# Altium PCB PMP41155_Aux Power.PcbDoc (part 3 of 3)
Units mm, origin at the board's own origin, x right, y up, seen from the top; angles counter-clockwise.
Board outline 40.5 x 70.5 mm, 6 copper layers (Top Layer, Signal Layer 1, Signal Layer 2, Signal Layer 3, Signal Layer 4, Bottom Layer), stack 1.573 mm thick; 130 components, 63 nets, 392 pads, 295 vias.
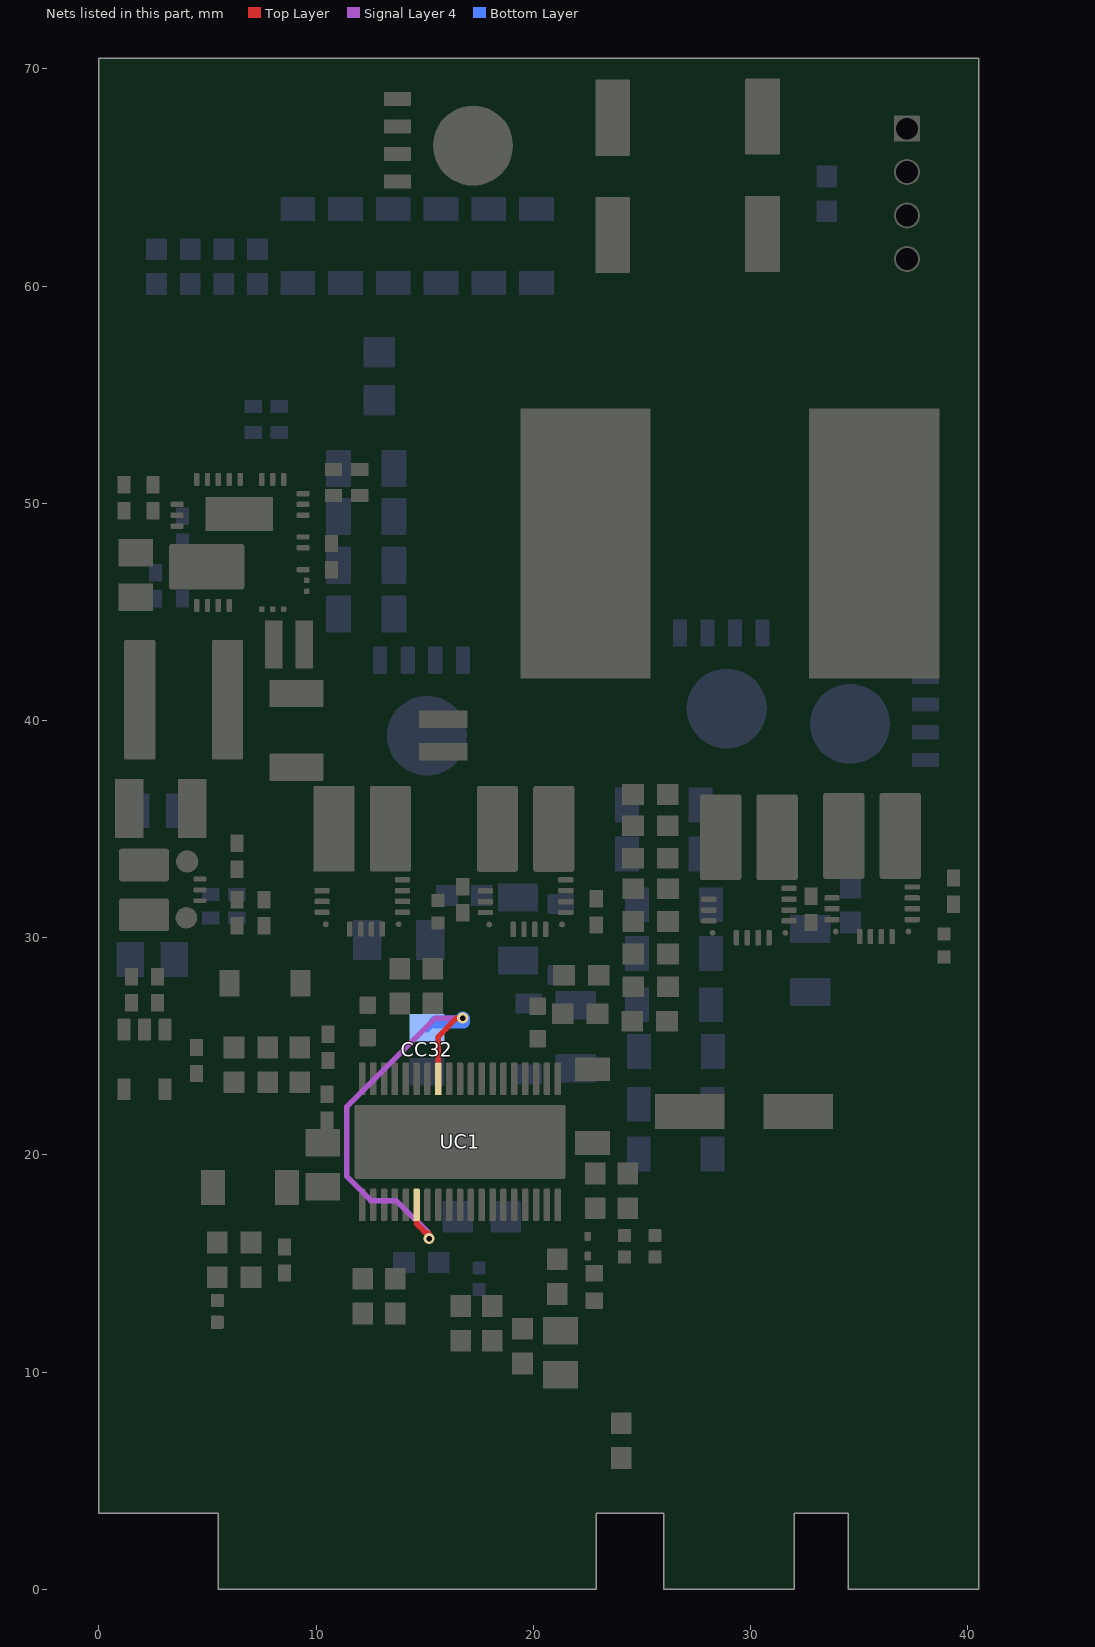
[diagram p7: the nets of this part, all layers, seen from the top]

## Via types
v1: diameter 0.508, hole 0.254, Top Layer to Bottom Layer, 138 vias
v2: diameter 0.5, hole 0.2, Top Layer to Bottom Layer, tented both sides, 64 vias
v3: diameter 0.5, hole 0.2, Top Layer to Bottom Layer, 48 vias
v4: diameter 0.6, hole 0.3, Top Layer to Bottom Layer, 29 vias
v5: diameter 1.27, hole 0.711, Top Layer to Bottom Layer, 8 vias
v6: diameter 0.5, hole 0.3, Top Layer to Bottom Layer, 7 vias
v7: diameter 0.508, hole 0.254, Top Layer to Bottom Layer, tented both sides, 1 vias

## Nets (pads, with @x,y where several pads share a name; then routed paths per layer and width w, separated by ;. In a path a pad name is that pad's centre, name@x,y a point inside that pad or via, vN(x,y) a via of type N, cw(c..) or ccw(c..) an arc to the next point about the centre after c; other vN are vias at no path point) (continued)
VCC_DISCH: CC32.1 UC1.6 UC1.31 | length 22.1
  Top Layer w0.254: UC1.6@14.625,17.7 14.625,16.827 14.632,16.827 14.959,16.5 14.959,16.491 15.048,16.402 v1@15.184,16.402 ; UC1.31@15.625,23.5 15.625,25.453 16.471,26.3 v1(16.75,26.3)
  Signal Layer 4 w0.254: v1@15.184,16.402 13.686,17.9 12.525,17.9 11.4,19.025 11.4,22.215 15.485,26.3 v1(16.75,26.3)
  Bottom Layer w0.254: CC32.1@15.1,25.766 CC32.1@15.48,26.146
  Bottom Layer w0.6: CC32.1@15.499,26.128 16.778,26.128 16.778,26.272 v1(16.75,26.3)
  other v1: 15.2,16.15
pads on no net: QC1.1 QC1.5 QC1.9 QC1.10 QC1.11 QC1.12 QC1.13 QC1.15 QC2.1 QC2.5 QC2.9 QC2.10 QC2.11 QC2.12 QC2.13 QC2.15 QC3.1 QC3.5 QC3.9 QC3.10 QC3.11 QC3.12 QC3.13 QC3.15 QC4.1 QC4.5 QC4.9 QC4.10 QC4.11 QC4.12 QC4.13 QC4.15 U1.7 U1.8 U1.10 U2.4 U3.2 U3.5 UC1.2 UC1.5 UC1.8 UC1.9 UC1.21 UC1.24 UC1.28 UC1.33
copper on no net:
  other v3: 1.585,32.85 2.085,32.85 2.585,32.85 1.585,33.85 2.085,33.85 2.585,33.85

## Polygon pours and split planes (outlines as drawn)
NetC3_1 on Top Layer "TOP_LAYER_NETC3_1_P262" (solid, pour order 262): 6.65,46 6.75,46.1 6.75,48.1 6.55,48.3 3.2,48.3 2.85,47.95 2.85,44.25 2.55,43.95 0.8,43.95 0.5,43.65 0.5,38.6 1.05,38.05 2.75,38.05 3.8,39.1 3.8,46
12V on Top Layer "TOP_LAYER_12V_P261" (solid, pour order 261): 11.95,69 12.45,69.5 14,69.5 14.35,69.15 14.35,64.35 14,64 12.3,64 11.95,64.35
SGND on Top Layer "TOP_LAYER_SGND_P258" (solid, pour order 258): 0.75,37.35 2.5,37.35 2.65,37.2 2.65,34.7 2.55,34.6 0.75,34.6
SGND on Top Layer "TOP_LAYER_SGND_P257" (solid, pour order 257): 10.15,38.55 11,39.4 11.7,39.4 12.05,39.05 12.05,37.4 11.85,37.2 7.85,37.2 7.85,38.55
12V on Top Layer "TOP_LAYER_12V_P256" (solid, pour order 256): 7.9,41.85 7.95,41.9 8.85,41.9 9.05,42.1 9.05,44.6 9.8,44.6 11.95,42.45 11.95,40.8 11.75,40.6 7.9,40.6 7.9,41.9
12V on Top Layer "TOP_LAYER_12V_P255" (solid, pour order 255): 4.65,33.1 4.65,34.3 5.65,35.3 5.65,37.3 3.65,37.3 3.5,37.15 3.5,32.5 3.95,32.5 3.95,33.1
5V on Top Layer "TOP_LAYER_5V_P252" (solid, pour order 252): 0.95,31.8 3.2,31.8 3.2,27.7 0.95,27.7
SGND on Top Layer "TOP_LAYER_SGND_P251" (solid, pour order 251): 4.25,45.6 4.45,45.8 6.5,45.8 6.8,45.5 6.8,44.5 6.55,44.25 4.4,44.25 4.25,44.4
NetL1_2 on Top Layer "TOP_LAYER_NETL1_2_P250" (solid, pour order 250): 8.45,44.6 7.4,44.6 6.8,44 5.55,44 5.5,43.95 5.5,38.35 6.95,38.35 7.1,38.5 7.1,41.95 7.55,42.4 8.45,42.4
12VFAN on Top Layer "TOP_LAYER_12VFAN_P249" (solid, pour order 249): 39.25,64.2 39.6,63.85 39.6,62.7 39.25,62.35 34.85,62.35 32.85,64.35 15.35,64.35 14.65,65.05 14.65,69.4 14.7,69.4 14.85,69.55 31.45,69.55 36.8,64.2
SGND on Top Layer "TOP_LAYER_SGND_P248" (solid, pour order 248): 34.6,62.15 39.1,62.15 39.55,61.7 39.55,59.75 39.25,59.45 22.8,59.45 22.4,59.85 22.4,63.7 22.8,64.1 32.65,64.1
VBATAUX on Top Layer "TOP_LAYER_VBATAUX_P246" (solid, pour order 246): 7.245,54.108 10.708,54.108 11.5,54.9 11.5,59.4 11.3,59.6 7.45,59.6 7.245,59.395
SGND on Top Layer "TOP_LAYER_SGND_P245" (solid, pour order 245): 1.2,69.15 6.35,69.15 8.997,69.15 9.8,68.347 9.8,64.25 9.05,63.5 6.74,63.5 6.45,63.138 6.45,52.55 1.8,52.55 1,53.35 1,68.95 1.1,69.05
CSB_DISCH on Top Layer "TOP_LAYER_CSB_DISCH_P239" (solid, pour order 239): 14.75,39.65 26.65,39.65 28,41 28,57 27.45,57.55 19.35,57.55 14.7,52.9 14.7,39.75
VAUX on Top Layer "TOP_LAYER_VAUX_P238" (solid, pour order 238): 29.6,32.5 29.6,36.45 28.35,37.7 28.35,38.7 27.9,39.15 25.65,39.15 25.25,38.75 25.25,24.3 30.1,24.3 30.1,25.95 27.5,28.55 27.5,31.65 28.75,31.65
SGND on Top Layer "TOP_LAYER_SGND_P230" (solid, pour order 230): 30.55,26.1 31.85,27.4 39.6,27.4 39.6,1.5 39.55,1.45 39.4,1.6 35.1,1.6 35.1,4.05 30.55,8.6
VAUX on Top Layer "TOP_LAYER_VAUX_P228" (solid, pour order 228): 27.05,4.5 27.05,20.95 27,20.95 26.75,21.2 24.9,21.2 22.7,23.4 21.95,23.4 21.95,24.5 30.1,24.5 30.1,5.15 29.45,4.5
SGND on Top Layer "TOP_LAYER_SGND_P227" (solid, pour order 227): 6.4,69 6.4,67.8 3.4,67.8 3.4,69
VBATAUX on Top Layer "TOP_LAYER_VBATAUX_P225" (solid, pour order 225): 9.099,55.602 9.099,54.902 7.299,54.902 7.299,55.602
SGND on Top Layer "TOP_LAYER_SGND_P226" (solid, pour order 226): 6.4,53.95 6.4,52.75 3.4,52.75 3.4,53.95
VBATAUX on Top Layer "TOP_LAYER_VBATAUX_P224" (solid, pour order 224): 9.1,56.85 9.1,56.15 7.3,56.15 7.3,56.85
VBATAUX on Top Layer "TOP_LAYER_VBATAUX_P223" (solid, pour order 223): 9.099,58.102 9.099,57.402 7.299,57.402 7.299,58.102
VBATAUX on Top Layer "TOP_LAYER_VBATAUX_P222" (solid, pour order 222): 9.1,59.35 9.1,58.65 7.3,58.65 7.3,59.35
no net on Top Layer "TOP_LAYER_NONET_P221" (solid, pour order 221): 9.099,60.602 9.099,59.902 7.299,59.902 7.299,60.602
no net on Top Layer "TOP_LAYER_NONET_P220" (solid, pour order 220): 9.1,61.85 9.1,61.15 7.3,61.15 7.3,61.85
no net on Top Layer "TOP_LAYER_NONET_P219" (solid, pour order 219): 9.099,63.102 9.099,62.402 7.299,62.402 7.299,63.102
SGND on Top Layer "TOP_LAYER_SGND_P218" (solid, pour order 218): 9.1,64.35 9.1,63.65 7.3,63.65 7.3,64.35
SGND on Top Layer "TOP_LAYER_SGND_P217" (solid, pour order 217): 9.099,65.602 9.099,64.902 7.299,64.902 7.299,65.602
SGND on Top Layer "TOP_LAYER_SGND_P216" (solid, pour order 216): 9.1,66.85 9.1,66.15 7.3,66.15 7.3,66.85
CSA_DISCH on Top Layer "TOP_LAYER_CSA_DISCH_P148" (solid, remove dead copper, pour order 148): 12.45,33.079 19.6,33.079 19.6,36.95 20.35,37.7 20.35,39.35 14.543,39.35 12.45,37.257
SGND on Top Layer "TOP_LAYER_SGND_P211" (solid, remove dead copper, pour order 211): 0.5,3.5 20.2,3.5 25.4,8.7 25.4,20.25 23.336,22.314 0.5,22.314
SGND on Top Layer "TOP_LAYER_SGND_P176" (solid, pour order 176): 35.7,36.647 37.693,36.647 39.023,37.977 39.532,37.977 39.532,34.074 38.962,33.503 38.282,33.503 37.532,32.753 35.7,32.753
SW2 on Top Layer "TOP_LAYER_SW2_P190" (solid, pour order 190): 39.2,54.5 40.048,53.652 40.052,39.502 37.702,37.152 37.093,37.152 37.093,37.043 36.8,36.75 36.8,32.75 30.15,32.75 30.15,36.35 28.85,37.65 28.85,52.65 30.7,54.5
SW2 on Top Layer "TOP_LAYER_SW2_P164" (solid, pour order 164): 29.59,36.662 36.454,36.662 36.454,32.626 33.655,32.626 33.319,32.962 32.464,32.962 32.06,32.558 29.769,32.558 29.55,32.777 29.55,36.622
SGND on Top Layer "TOP_LAYER_SGND_P177" (solid, pour order 177): 23.45,33.068 23.65,32.868 23.65,24.05 25.05,24.05 25.05,30.25 25.05,38.85 24.76,39.14 22.09,39.14 19.8,36.85 19.8,33.068
5V on Top Layer "5V" (solid, remove dead copper, pour order 42): 6,11.05 6,9.85 6.2,9.65 11.184,9.65 11.217,9.683 11.217,10.964 10.981,11.2 6.15,11.2
SGND on Bottom Layer "BOTTOM_LAYER_SGND_P264" (solid, pour order 264): 4.85,50.4 7.95,50.4 8.25,50.1 8.25,48.4 7.9,48.05 6.8,48.05 6.45,47.7 6.45,45.25 4.7,45.25 4.45,45.5 4.45,50.05 4.85,50.45
SGND on Bottom Layer "BOTTOM_LAYER_SGND_P263" (solid, pour order 263): 5.8,46 6.9,44.9 6.9,43.25 6.4,42.75 0.7,42.75 0.5,42.95 0.5,45.75 0.75,46
12V on Bottom Layer "BOTTOM_LAYER_12V_P260" (solid, pour order 260): 4.65,33.1 4.65,34.3 5.65,35.3 5.65,37.3 3.65,37.3 3.05,36.7 3.05,32.5 3.95,32.5 3.95,33.1
VBATAUX on Bottom Layer "BOTTOM_LAYER_VBATAUX_P259" (solid, pour order 259): 1,60.2 1.5,60.7 20.85,60.7 21.9,59.65 21.9,57.4 14.6,57.4 13.35,56.15 11.55,56.15 11.1,55.7 11.1,54.4 10.75,54.05 10.7,54.1 9.55,54.1 9.55,54.15 9.15,54.55 9.15,56.3 6.35,59.1 1.4,59.1 1,59.5
5V on Bottom Layer "BOTTOM_LAYER_5V_P254" (solid, pour order 254): 2.75,31.8 2.85,31.7 2.85,30.2 2.55,29.9 2.55,28.65 2.1,28.2 0.8,28.2 0.8,31.7 0.9,31.8
SGND on Bottom Layer "BOTTOM_LAYER_SGND_P253" (solid, pour order 253): 2.85,29.8 4.1,29.8 4.25,29.65 4.25,26.85 4,26.6 2.95,26.6 2.85,26.7
SGND on Bottom Layer "BOTTOM_LAYER_SGND_P247" (solid, pour order 247): 1,68.95 1.55,69.5 39.05,69.5 39.5,69.05 39.5,64.7 36.05,61.25 1.55,61.25 1,61.8
VAUX on Bottom Layer "BOTTOM_LAYER_VAUX_P243" (solid, pour order 243): 7.1,45.35 9.25,45.35 9.85,44.75 9.85,44.25 10,44.1 11.6,44.1 12.2,44.7 12.2,52 11.8,52.4 10,52.4 8.5,50.9 8.5,48.25 8.15,47.9 7.05,47.9 6.95,47.8 6.95,45.5
SGND on Bottom Layer "BOTTOM_LAYER_SGND_P241" (solid, pour order 241): 18.35,32.5 18.35,31.2 20.25,31.2 20.25,32.2 20.55,32.5 25.6,32.5 25.6,41.45 14.4,52.65 12.6,52.65 12.6,44.7 12.6,42.15 13.15,41.6 18.35,41.6 19.95,40 19.95,32.8 19.65,32.5
SGND on Bottom Layer "BOTTOM_LAYER_SGND_P046" (solid, pour order 46): 37.304,42.545 37.309,42.55 39.65,42.55 39.95,42.25 39.95,30.45 39.45,29.95 36.15,29.95 35.85,30.25 35.85,36.7 36.4,37.25 37.15,37.25 37.3,37.4 37.3,42.55
SGND on Bottom Layer "BOTTOM_LAYER_SGND_P054" (solid, pour order 54): 25.6,19.2 25.6,37.3 25.3,37.6 23.75,37.6 23.45,37.3 23.45,19.8 24.05,19.2
SGND on Bottom Layer "BOTTOM_LAYER_SGND_P237" (solid, pour order 237): 30.55,26.85 31.85,28.15 39.6,28.15 39.6,1.5 39.55,1.45 39.4,1.6 35.1,1.6 35.1,4.05 30.55,8.6
SGND on Bottom Layer "BOTTOM_LAYER_SGND_P236" (solid, remove dead copper, pour order 236): 0.45,4.25 1.2,3.5 22.2,3.5 23.027,4.327 23.027,22.123 22.836,22.314 2.193,22.314 0.45,20.404
VAUX on Bottom Layer "Bottom Layer-48V_DISCH_OUT" (solid, remove dead copper, pour order 180): 26.189,42.734 25.78,42.325 25.78,32.35 26.565,31.797 26.565,24.513 23.9,21.849 23.9,9.336 23.9,4.082 24.109,3.873 25.259,3.873 29.345,3.873 29.65,4.177 29.65,32.871 29.95,33.158 29.95,35.998 31.544,37.592 31.544,42.262 31.071,42.735 26.215,42.735
NetC2_2 on Bottom Layer "BOTTOM_LAYER_NETC2_2_P234" (solid, remove dead copper, pour order 234): 17.157,32.42 17.157,29.505 18.362,28.3 20.212,28.3 20.212,29.6 18.912,29.6 18.112,30.4 18.123,30.411 18.123,32.42
SW2 on Bottom Layer "Bottom Layer-SW2" (solid, pour order 215): 28.535,32.955 29.872,31.619 34.776,31.619 35.645,32.488 35.645,36.654 36.348,37.356 39.75,37.356 39.75,56.05 38.3,57.5 27.5,57.5 26.495,56.495 26.495,43.35 31.995,43.35 31.995,36.431 29.01,36.431 28.535,35.956
CSA_DISCH on Bottom Layer "BOTTOM_LAYER_CSA_DISCH_P144" (solid, pour order 144): 12.328,41.078 12.6,41.35 17.7,41.35 19.44,39.61 19.44,32.744 12.328,32.744
5V on Bottom Layer "5V" (solid, remove dead copper, pour order 194): 6.15,11.2 5.95,11 5.95,9.7 6.15,9.5 11.354,9.5 11.55,9.696 11.55,11.967 11.217,12.3 10.406,12.3 10.191,12.085 10.191,11.691 9.7,11.2
NetC1_2 on Bottom Layer "BOTTOM_LAYER_NETC1_2_P195" (solid, pour order 195): 35.325,31.2 35.325,30.225 34.905,29.805 31.79,29.805 31.79,31.2
VBATAUX on Signal Layer 3 "SIGNAL_LAYER_3_VBATAUX_P244" (solid, pour order 244): 11.9,33.4 11.9,44.7 20,52.8 20,62.65 15.6,67.05 8.15,67.05 5.5,64.4 5.5,37.5 9.6,33.4
SGND on Signal Layer 3 "SIGNAL_LAYER_3_SGND_P232" (solid, pour order 232): 26,24.65 28.75,27.4 39.6,27.4 39.6,1.5 39.55,1.45 39.4,1.6 35.1,1.6 35.1,4.15 26,13.25
SGND on Signal Layer 3 "SGND" (solid, remove dead copper, pour order 199): 3.5,4.2 4.2,3.5 22.2,3.5 23.75,5.05 23.75,21.9 23.336,22.314 5.1,22.314 3.5,20.561
CSA_DISCH on Signal Layer 3 "SIGNAL_LAYER_3_CSA_DISCH_P163" (solid, pour order 163): 12.12,39.541 13.329,40.75 13.395,40.75 18.843,40.75 18.888,40.75 19.8,39.838 19.8,33.086 16.286,33.086 16.276,33.097 12.12,33.097
SGND on Signal Layer 3 "SGND" (solid, remove dead copper, pour order 182): 17.8,8 18.745,8 18.95,7.795 18.95,6.152 18.148,5.35 9,5.35 6.75,7.6 6.75,10.85 6.15,11.45 6,11.6 6,13 6.15,13.15 11.35,13.15 13.403,11.097 14.697,11.097
SGND on Signal Layer 4 "SIGNAL_LAYER_4_SGND_P240" (solid, remove dead copper, pour order 240): 0,69.3 0,22.7 39.6,22.7 39.6,69.3
VAUX on Signal Layer 4 "Bottom Layer-48V_DISCH_OUT" (solid, remove dead copper, pour order 235): 26.189,42.734 25.78,42.325 25.78,32.35 26.565,31.797 26.565,24.513 23.9,21.849 23.9,9.336 23.9,4.082 24.109,3.873 25.259,3.873 29.345,3.873 29.65,4.177 29.65,32.871 29.95,33.158 29.95,35.998 31.544,37.592 31.544,42.262 31.071,42.735 26.215,42.735
SGND on Signal Layer 4 "SIGNAL_LAYER_4_SGND_P233" (solid, pour order 233): 30.55,26.1 31.85,27.4 39.6,27.4 39.6,1.5 39.55,1.45 39.4,1.6 35.1,1.6 35.1,4.05 30.55,8.6
SGND on Signal Layer 4 "SIGNAL_LAYER_4_SGND_P214" (solid, remove dead copper, pour order 214): 4.95,3.85 5.3,3.5 22.2,3.5 23.437,4.737 23.437,22.213 23.336,22.314 5.1,22.314 4.95,22.15
CSA_DISCH on Signal Layer 4 "SIGNAL_LAYER_4_CSA_DISCH_P184" (solid, remove dead copper, pour order 184): 15.849,41.15 20.653,41.15 21.1,40.696 21.1,38.109 19.65,36.659 19.65,33.672 19.251,33.001 14.799,28.549 11.54,28.549 7.878,24.887 5.015,24.887 5.015,25.928 5.015,27.615 10.474,33.074 12.161,33.074 12.161,37.462
SGND on Signal Layer 2 "SIGNAL_LAYER_2_SGND_P229" (solid, pour order 229): 30.55,26.1 31.85,27.4 39.6,27.4 39.6,1.5 39.55,1.45 39.4,1.6 35.1,1.6 35.1,4.05 30.55,8.6
SGND on Signal Layer 2 "SIGNAL_LAYER_2_SGND_P213" (solid, remove dead copper, pour order 213): 4.95,3.85 5.3,3.5 22.15,3.5 23.437,4.787 23.437,22.213 23.336,22.314 5.1,22.314 4.95,22.15
SGND on Signal Layer 2 "SIGNAL_LAYER_2_SGND_P196" (solid, remove dead copper, pour order 196): 0,69.3 0,22.7 39.6,22.7 39.6,69.3
CSA_DISCH on Signal Layer 2 "SIGNAL_LAYER_2_CSA_DISCH_P191" (solid, remove dead copper, pour order 191): 21.25,40.65 20.8,41.1 20.8,41.15 15.849,41.15 12.161,37.462 12.161,32.769 10.069,32.769 5.015,27.715 5.015,25.928 5.015,24.887 7.878,24.887 11.54,28.549 14.799,28.549 19.251,33.001 19.45,33.336 19.45,36.459 21.25,38.259
no net on Top Solder "NONET_L-01_P-001" (solid): 3.4,69 6.4,69 6.4,67.8 3.4,67.8
no net on Top Solder "NONET_L-01_P-001" (solid): 3.4,53.95 6.4,53.95 6.4,52.75 3.4,52.75
no net on Top Solder "NONET_L-01_P-001" (solid): 7.3,55.6 9.1,55.6 9.1,54.9 7.3,54.9
no net on Top Solder "NONET_L-01_P-001" (solid): 7.3,56.85 9.1,56.85 9.1,56.15 7.3,56.15
no net on Top Solder "NONET_L-01_P-001" (solid): 7.3,58.1 9.1,58.1 9.1,57.4 7.3,57.4
no net on Top Solder "NONET_L-01_P-001" (solid): 7.3,59.35 9.1,59.35 9.1,58.65 7.3,58.65
no net on Top Solder "NONET_L-01_P-001" (solid): 7.3,60.6 9.1,60.6 9.1,59.9 7.3,59.9
no net on Top Solder "NONET_L-01_P-001" (solid): 7.3,61.85 9.1,61.85 9.1,61.15 7.3,61.15
no net on Top Solder "NONET_L-01_P-001" (solid): 7.3,63.1 9.1,63.1 9.1,62.4 7.3,62.4
no net on Top Solder "NONET_L-01_P-001" (solid): 7.3,64.35 9.1,64.35 9.1,63.65 7.3,63.65
no net on Top Solder "NONET_L-01_P-001" (solid): 7.3,65.6 9.1,65.6 9.1,64.9 7.3,64.9
VBATAUX on Top Solder "NONET_L-01_P-001" (solid): 7.3,66.85 9.1,66.85 9.1,66.15 7.3,66.15
SGND on Top Solder "NONET_L-01_P-001" (solid): 34.5,0 40.5,0 40.5,3.5 34.5,3.5
VAUX on Top Solder "NONET_L-01_P-001" (solid): 26,0 32,0 32,3.5 26,3.5
VAUX on Signal Layer 1 "SIGNAL_LAYER_1_VAUX_P242" (solid, pour order 242): 23.65,26.2 30,32.55 30,44.3 26.25,48.05 6.45,48.05 5.1,46.7 5.1,29.4 8.3,26.2
SGND on Signal Layer 1 "SIGNAL_LAYER_1_SGND_P231" (solid, pour order 231): 30.55,34.4 33.05,36.9 39.6,36.9 39.6,1.5 39.55,1.45 39.4,1.6 35.1,1.6 35.1,4.05 30.55,8.6
SGND on Signal Layer 1 "SIGNAL_LAYER_1_SGND_P212" (solid, remove dead copper, pour order 212): 0,5.5 2,3.5 22.2,3.5 23.437,4.737 23.437,22.213 23.336,22.314 2.063,22.314 0,20.054
no net on Bottom Solder "NONET_L-01_P-001" (solid): 26,0 32,0 32,3.5 26,3.5
no net on Bottom Solder "NONET_L-01_P-001" (solid): 34.5,0 40.5,0 40.5,3.5 34.5,3.5

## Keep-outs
Keep-Out Layer:
  text ".Layer_Name" at 14.656,-21.806 h1.52

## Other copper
Top Layer:
  rectangle net SGND: 11.3,0.25 12.3,4.25
  rectangle net UC_FAN_PWM: 8.9,0.25 9.9,4.25
  rectangle net UC_FAN_CLK: 6.5,0.25 7.5,4.25
  rectangle net UC_En_Disable_AUX: 13.7,0.25 14.7,4.25
  rectangle net UC_VFB_DIR_AUX: 20.9,0.25 21.9,4.25
  rectangle net UC_COMP_DIR_AUX: 18.5,0.25 19.5,4.25
  rectangle net UC_MODE_AUX: 16.1,0.25 17.1,4.25
  region net SGND: 40.488,3.624 38.838,5.274 36.288,5.274 34.488,3.474 34.488,-0.026 40.488,-0.026
  region net VAUX: 32,3.65 30.35,5.3 27.8,5.3 26,3.5 26,0 32,0
  text ".Layer_Name" at 14.656,-21.806 h1.52
Signal Layer 4:
  pour cut-out: 17.45,39.45 17.25,39.25 17.25,38.95 17.45,38.75 17.8,38.75 17.95,38.9 17.95,39.25 17.75,39.45
  pour cut-out: 7.389,26.238 7.599,26.447 8.041,26.447 8.251,26.238 8.251,25.662 8.108,25.519 7.532,25.519 7.389,25.662
Signal Layer 3:
  pour cut-out: 18.378,37.862 18.378,40.244 16.952,40.244 16.952,39.837 14.857,37.742 14.857,33.097 16.5,33.097 16.5,36.062
Signal Layer 1:
  pour cut-out: 11.35,24.45 11.2,24.3 11.2,23.85 11.35,23.7 11.75,23.7 11.9,23.85 11.9,24.3 11.75,24.45 11.5,24.45
Signal Layer 2:
  pour cut-out: 8.05,26.4 7.7,26.4 7.5,26.2 7.5,25.9 7.7,25.7 8.05,25.7 8.2,25.85 8.2,26.25
  pour cut-out: 17.75,39.45 17.45,39.45 17.25,39.25 17.25,38.95 17.449,38.751 17.751,38.751 17.95,38.95 17.95,39.25
Bottom Layer:
  rectangle net 5V: 13.7,0.25 14.7,4.25
  rectangle net SGND: 18.5,0.25 19.5,4.25
  rectangle net SGND: 11.3,0.25 12.3,4.25
  rectangle net SGND: 6.5,0.25 7.5,4.25
  rectangle net 12V: 20.9,0.25 21.9,4.25
  rectangle: 16.1,0.25 17.1,4.25
  rectangle net 3V3: 8.9,0.25 9.9,4.25
  region net SGND: 40.488,3.624 38.838,5.274 36.288,5.274 34.488,3.474 34.488,-0.026 40.488,-0.026
  region net VAUX: 32,3.65 30.35,5.3 27.8,5.3 26,3.5 26,0 32,0
  pour cut-out: 17.5,39.45 17.3,39.25 17.3,38.95 17.5,38.75 17.75,38.75 17.95,38.95 17.95,39.25 17.75,39.45
  text ".Layer_Name" at 14.656,-21.806 h1.52

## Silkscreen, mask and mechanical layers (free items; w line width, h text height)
Top Overlay:
  lines w0.254: 44,46.55 44,46.55
  text ".Layer_Name" at 14.656,-21.806 h1.52
Bottom Overlay:
  text "PMP41155_AUX" at 33.45,67.35 h2.75
  text ".Layer_Name" at 14.656,-21.806 h1.52
Top Paste:
  text ".Layer_Name" at 14.656,-21.806 h1.52
Bottom Paste:
  text ".Layer_Name" at 14.656,-21.806 h1.52
Top Solder:
  rectangle: 20.789,0.036 22.039,4.25
  rectangle: 18.389,0.036 19.639,4.25
  rectangle: 6.25,0.036 7.75,4.25
  rectangle: 8.75,0 10,4.25
  rectangle: 11,0 12.5,4.25
  rectangle: 13.5,0.036 15,4.25
  rectangle: 16,0.036 17.25,4.25
  text ".Layer_Name" at 14.656,-21.806 h1.52
  text ".Layer_Name" at 14.656,-21.806 h1.52
Bottom Solder:
  region: 23.834,37.776 23.834,42.2 20.55,42.2 20.55,37.776
  rectangle: 20.8,0.009 22.05,4.259
  rectangle: 18.381,0 19.631,4.25
  rectangle: 16,0 17.25,4.25
  rectangle: 13.5,0 14.75,4.25
  rectangle: 11,0 12.5,4.25
  rectangle: 8.75,0 10,4.25
  rectangle: 6.25,0 7.75,4.25
  region: 39.567,54.15 34.2,54.15 34.2,44.35 39.567,44.35
  rectangle: 31.9,9.75 36.85,26.372
  region: 31.3,61.95 31.3,64.4 23.076,64.4 23.076,61.95
  rectangle: 26.777,44.8 34.15,49.811
  text ".Layer_Name" at 14.656,-21.806 h1.52
Drill Guide:
  text ".Layer_Name" at 14.656,-21.806 h1.52
M1 Board Outline:
  lines w0.254: 40.5,0 34.5,0 34.5,3.5 32,3.5 32,0 26,0 26,3.5 22.9,3.5 22.9,0 5.5,0 5.5,3.5 0,3.5 0,70.5 10,70.5 15,70.5 40.5,70.5 40.5,3.5 40.5,0.036
  text ".Layer_Name" at 14.656,-21.806 h1.52
M2 Board Dimensions:
  rectangle: 0,-6.985 3.175,-3.81
  rectangle: 3.175,-10.16 12.7,-6.985
  lines w0.178: 0,-6.985 25.4,-6.985 ; 3.175,-10.16 3.175,-3.81 ; 6.35,-10.16 6.35,-3.81 ; 12.7,-10.16 12.7,-3.81 ; 19.05,-10.16 19.05,-3.81 ; 0,-10.16 25.4,-10.16 25.4,-3.81 0,-3.81 0,-10.16
  text ".Layer_Name" at 14.656,-21.806 h1.52
M3 3D STEP Top:
  text ".Layer_Name" at 14.656,-21.806 h1.52
M4 3D STEP Bottom:
  text ".Layer_Name" at 14.656,-21.806 h1.52
M5 Assembly Top:
  lines w0.254: -7.417,-23.626 160.223,-23.626 ; -7.417,-18.462 160.274,-18.462 ; -7.417,-13.297 -7.417,-28.791 94.31,-28.791 160.274,-28.791 160.274,-13.297 -7.404,-13.297 -7.404,-28.791 32.614,-28.791 ; 55.194,-28.791 55.194,-13.297 ; 87.376,-18.462 87.376,-13.297 ; 108.712,-18.462 108.712,-13.297 ; 124.511,-28.956 124.511,-23.804
  text "COMPONENTS MARKED 'DNP' SHOULD NOT BE POPULATED." at 29.299,-8.09 h1.52
  text "ASSEMBLY VARIANT:" at 29.286,-11.024 h1.52
  text ".VariantName" at 55.601,-11.024 h1.52
  text "PCB VIEWED FROM TOP SIDE" at -5.804,-16.654 h1.52
  text "BOARD #:" at 57.099,-16.654 h1.52
  text ".PRJ_Number" at 70.955,-16.654 h1.52
  text "REV:" at 92.405,-16.654 h1.52
  text ".PCB_Rev" at 99.809,-16.654 h1.52
  text "SVN REV:" at 113.69,-16.654 h1.52
  text ".VersionControl_RevNumber" at 126.543,-16.654 h1.52
  text "TID #:" at 57.099,-21.819 h1.52
  text ".TID" at 70.955,-21.819 h1.52
  text "PLOT NAME =" at -5.804,-27.034 h1.52
  text ".plot_File_Name" at 14.656,-27.034 h1.52
  text "GENERATED    :" at 57.15,-27.034 h1.52
  text ".Print_Date" at 79.235,-27.034 h1.52
  text ".Print_Time" at 97.752,-27.034 h1.52
  text "TEXAS INSTRUMENTS" at 129.87,-27.034 h1.52
M6 Assembly Bottom:
  lines w0.254: -7.429,-18.474 160.261,-18.474 ; -7.379,-23.639 160.261,-23.639 ; 28.334,-28.969 28.334,-23.817 ; 44.133,-18.474 44.133,-13.31 ; 65.468,-18.474 65.468,-13.31 ; 97.65,-28.804 97.65,-13.31 ; 120.231,-28.804 160.249,-28.804 160.249,-13.31 -7.429,-13.31 -7.429,-28.804 58.534,-28.804 160.261,-28.804 160.261,-13.31
  text "COMPONENTS MARKED 'DNP' SHOULD NOT BE POPULATED." at 154.991,-8.077 h1.52
  text ".VariantName" at 128.473,-11.024 h1.52
  text "ASSEMBLY VARIANT:" at 154.864,-11.024 h1.52
  text ".VersionControl_RevNumber" at 26.302,-16.667 h1.52
  text "SVN REV:" at 39.154,-16.667 h1.52
  text ".PCB_Rev" at 53.035,-16.667 h1.52
  text "REV:" at 60.439,-16.667 h1.52
  text ".PRJ_Number" at 81.89,-16.667 h1.52
  text "BOARD #:" at 95.745,-16.667 h1.52
  text "PCB VIEWED FROM BOTTOM SIDE" at 158.648,-16.667 h1.52
  text ".TID" at 81.89,-21.831 h1.52
  text "TID #:" at 95.745,-21.831 h1.52
  text "TEXAS INSTRUMENTS" at 22.974,-27.047 h1.52
  text ".Print_Time" at 55.093,-27.047 h1.52
  text ".Print_Date" at 73.609,-27.047 h1.52
  text "GENERATED    :" at 95.694,-27.047 h1.52
  text ".plot_File_Name" at 138.189,-27.047 h1.52
  text "PLOT NAME =" at 158.648,-27.047 h1.52
M9 Title Sheet:
  drawing of 57 lines, arcs and shapes, not listed
  text "1" at 18.792,204.127 h1.78
  text "2" at 82.182,204.127 h1.78
  text "3" at 145.411,204.127 h1.78
  text "4" at 209.08,204.127 h1.78
  text "5" at 272.555,204.127 h1.78
  text "6" at 336.182,204.127 h1.78
  text "A" at -10.579,175.095 h1.78
  text "A" at 365.341,175.095 h1.78
  text "B" at -10.579,114.643 h1.78
  text "B" at 365.341,114.643 h1.78
  text "C" at -10.579,54.318 h1.78
  text "C" at 365.341,54.318 h1.78
  text "PROJECT TITLE:" at 288.125,7.048 h1.14
  text ".PRJ_Title" at 289.395,3.662 h1.78
  text "DESIGNED FOR:" at 288.125,-0.597 h1.14
  text ".PRJ_Customer" at 289.395,-4.153 h1.78
  text "D" at -10.579,-5.88 h1.78
  text "D" at 365.341,-5.88 h1.78
  text "FILE NAME:" at 288.125,-8.217 h1.14
  text ".PCB_File_Name_No_Path" at 289.395,-11.265 h1.78
  text "Texas Instruments (TI) and/or its licensors do not warrant the accuracy or completeness of this specification" at 161.9,-15.376 h1.14
  text "ENGINEER:" at 288.125,-15.583 h1.14
  text "LAYOUT BY:" at 326.352,-15.583 h1.14
  text "or any information contained therein. TI and/or its licensors do not warrant that this design will meet" at 160.757,-18.237 h1.14
  text ".PRJ_Engineer" at 289.395,-19.52 h1.78
  text ".PCB_Layout" at 327.635,-19.52 h1.78
  text "the specifications, will be suitable for your application or fit for any particular purpose, or will operate in" at 160.757,-21.099 h1.14
  text ".Layer_Name" at 14.656,-21.806 h1.52
  text "ALTIUM DESIGNER VERSION:" at 326.352,-23.457 h1.14
  text "an implementation. TI and/or its licensors do not warrant that the design is production worthy. You should" at 160.757,-23.961 h1.14
  text "completely validate and test your design implementation to confirm the system functionality for your application." at 161.9,-26.822 h1.14
  text ".print_Scale" at 289.395,-26.843 h1.78
  text ".Application_BuildNumber" at 327.635,-26.843 h1.78
  text "1" at 18.792,-32.093 h1.78
  text "2" at 82.182,-32.093 h1.78
  text "3" at 145.411,-32.093 h1.78
  text "4" at 209.08,-32.093 h1.78
  text "5" at 272.555,-32.093 h1.78
  text "6" at 336.182,-32.093 h1.78
M10 Fab Notes:
  drawing of 189 lines, arcs and shapes, not listed
  text "DESIGN INFORMATION" at 314.503,161.447 h1.52
  text "MIN. TRACK WIDTH:" at 298.131,158.091 h1.52
  text "8" at 325.976,158.091 h1.52
  text "MIL" at 329.907,158.091 h1.52
  text "MIN. CLEARANCE:" at 298.131,154.938 h1.52
  text "0.2" at 324.452,154.938 h1.52
  text "mm" at 329.907,154.938 h1.52
  text "MIN. VIA PAD SIZE:" at 298.131,151.785 h1.52
  text "24" at 325.214,151.785 h1.52
  text "MIL" at 329.907,151.785 h1.52
  text "0.05mm (2MIL)" at 315.784,148.486 h1.52
  text "MINIMUM ANNULAR RING" at 289.769,148.277 h1.52
  text "EXTERNAL" at 333.768,148.277 h1.52
  text "PER" at 294.849,145.48 h1.52
  text "IPC-D-275 CLASS 2 LEVEL C" at 300.437,145.48 h1.52
  text "MIL, HOLES" at 338.238,142.928 h1.52
  text "+/-" at 328.27,142.709 h1.52
  text "+/-" at 349.961,142.709 h1.52
  text "REGISTRATION TOLERANCES:" at 289.769,142.682 h1.52
  text "METAL" at 320.243,142.682 h1.52
  text "5" at 334.879,142.683 h1.52
  text "3" at 356.037,142.683 h1.52
  text "MIL" at 358.99,142.682 h1.52
  text "HOLE SIZE TOLERANCE (UNLESS OTHERWISE SPECIFIED):" at 289.769,140.185 h1.52
  text "+/-" at 349.961,140.112 h1.52
  text "3" at 356.037,140.085 h1.52
  text "MIL" at 358.99,140.085 h1.52
  text "MATERIAL:" at 287.87,136.589 h1.52
  text "FR-4 High Tg" at 312.926,133.324 h1.52
  text "X" at 309.257,133.122 h1.52
  text "FR-408" at 298.563,133.007 h1.52
  text "OTHER" at 336.358,133.007 h1.52
  text "62 MIL (1.6mm) +/-10%" at 306.694,129.374 h1.52
  text "X" at 303.643,129.312 h1.52
  text "THICKNESS:" at 289.769,129.165 h1.52
  text "OTHER" at 339.33,129.165 h1.52
  text "TOLERANCE:" at 289.769,125.652 h1.52
  text "X" at 311.314,125.652 h1.52
  text "ANSI IPC-6012 TYPE 3 CLASS 2" at 315.836,125.652 h1.52
  text "OTHER +/-" at 315.835,121.989 h1.52
  text "BOW & TWIST:" at 289.769,118.302 h1.52
  text "X" at 311.314,118.302 h1.52
  text "ANSI IPC-6012 TYPE 3 CLASS 2" at 315.836,118.302 h1.52
  text "OTHER +/-" at 315.835,114.576 h1.52
  text "DRILLING:" at 287.87,111.258 h1.52
  text "NC_DRILL FILES" at 332.599,108.586 h1.52
  text "REFERENCE:" at 289.769,108.486 h1.52
  text "X" at 306.463,108.484 h1.52
  text "AS SHOWN" at 310.984,108.486 h1.52
  text "X" at 329.348,108.486 h1.52
  text "OTHER" at 340.168,104.873 h1.52
  text "PTH COPPER THICKNESS:" at 289.761,104.783 h1.52
  text "X" at 318.697,104.783 h1.52
  text "20-30 um" at 321.948,104.783 h1.52
  text "BOARD FINISH:" at 287.87,101.034 h1.52
  text "SILKSCREEN:" at 291.812,98.237 h1.52
  text "X" at 316.14,98.237 h1.52
  text "TOP" at 319.112,98.237 h1.52
  text "X" at 329.094,98.237 h1.52
  text "BOTTOM" at 332.091,98.237 h1.52
  text "SILKSCREEN COLOR:" at 291.812,94.295 h1.52
  text "X" at 316.115,94.295 h1.52
  text "WHITE" at 319.112,94.295 h1.52
  text "OTHER" at 332.091,94.295 h1.52
  text "X" at 319.442,90.652 h1.52
  text "GREEN" at 322.439,90.652 h1.52
  text "OTHER" at 338.136,90.652 h1.52
  text "SOLDER RESIST COLOR:" at 291.812,90.477 h1.52
  text "X" at 319.442,86.734 h1.52
  text "MATTE" at 322.439,86.734 h1.52
  text "SEMI-GLOSS" at 338.125,86.717 h1.52
  text "IMMERSION GOLD (ENIG)" at 314.819,82.345 h1.52
  text "ENEPIG" at 348.793,82.162 h1.52
  text "SURFACE FINISH:" at 287.87,82.136 h1.52
  text "X" at 310.298,82.136 h1.52
  text "IMM. TIN/SILVER OR EQUIV" at 296.24,78.649 h1.52
  text "OTHER" at 332.599,78.549 h1.52
  text "ARRAY/PANEL:" at 287.87,74.602 h1.52
  text "CUT AND TRIM PER M1 BOARD OUTLINE" at 314.819,74.393 h1.52
  text "N.C. ROUTE" at 314.819,70.94 h1.52
  text "X" at 332.295,70.94 h1.52
  text "V. SCORE" at 336.816,70.94 h1.52
  text "CERTIFICATION:" at 287.87,67.66 h1.52
  text "MATERIALS AND WORKMANSHIP FOR ALL PCBS" at 306.285,67.66 h1.52
  text "TO MEET OR EXCEED THE REQUIREMENTS OF:" at 306.285,65.271 h1.52
  text "X" at 297.078,62.003 h1.52
  text "ANSI IPC-A-600F CLASS ->" at 300.329,62.003 h1.52
  text "X" at 342.188,62.003 h1.52
  text "2" at 344.982,62.003 h1.52
  text "1" at 336.981,61.965 h1.52
  text "3" at 353.973,61.965 h1.52
  text "X" at 317.702,58.252 h1.52
  text "RoHS" at 320.953,58.252 h1.52
  text "OTHER" at 337.321,58.252 h1.52
  text "PER ORDER" at 347.407,58.252 h1.52
  text "ALL BOARDS MUST MEET OR EXCEED UL94-V0 REQUIREMENTS." at 288.569,54.345 h1.52
  text "PCB MUST BEAR THE UL94V-0 UL REGISTERED MATERIAL ID NUMBER" at 288.569,51.397 h1.52
  text "ADDITIONAL REQUIREMENTS:" at 287.87,47.094 h1.52
  text "MICROSECTION:" at 289.769,44.373 h1.52
  text "YES" at 312.775,44.373 h1.52
  text "REQUIRED" at 334.657,40.707 h1.52
  text "BARE BOARD ELEC. TEST:" at 289.769,40.634 h1.52
  text "NONE" at 322.935,40.634 h1.52
  text "X" at 331.66,40.634 h1.52
  text "PER ORDER" at 349.693,40.634 h1.52
  text "XX MIL VIAS REQUIRE NON-CONDUCTIVE FILL AND PLANARIZE" at 294.04,35.428 h1.5
  text "XX MIL VIAS REQUIRE CONDUCTIVE FILL AND PLANARIZE" at 294.243,32.787 h1.52
  text "OUTER XX MIL TRACES REQUIRE 50 OHM SINGLE-ENDED IMPEDANCE" at 294.218,28.637 h1.47
  text "LAYER 2 & 3 (INNER LAYERS) XX MIL WIDE, XX MIL SPACE / TRACES REQUIRE 100 OHM DIFFERENTIAL IMPEDANCE" at 294.015,22.65 h1.52
  text ".Layer_Name" at 14.656,-21.806 h1.52
M11 Gerber Information:
  lines w0.254: -7.417,-23.626 160.223,-23.626 ; -7.417,-18.462 160.274,-18.462 ; -7.417,-13.297 -7.417,-28.791 94.31,-28.791 160.274,-28.791 160.274,-13.297 -7.404,-13.297 -7.404,-28.791 32.614,-28.791 ; 55.194,-28.791 55.194,-13.297 ; 87.376,-18.462 87.376,-13.297 ; 108.712,-18.462 108.712,-13.297 ; 124.511,-28.956 124.511,-23.804
  text "ALL ARTWORK VIEWED FROM TOP SIDE" at -5.804,-16.654 h1.52
  text "BOARD #:" at 57.099,-16.654 h1.52
  text ".PRJ_Number" at 70.955,-16.654 h1.52
  text "REV:" at 92.405,-16.654 h1.52
  text ".PCB_Rev" at 99.809,-16.654 h1.52
  text "SVN REV:" at 113.69,-16.654 h1.52
  text ".VersionControl_RevNumber" at 126.543,-16.654 h1.52
  text "LAYER NAME =" at -5.804,-21.806 h1.52
  text "TID #:" at 57.099,-21.819 h1.52
  text ".TID" at 70.955,-21.819 h1.52
  text "PLOT NAME =" at -5.804,-27.034 h1.52
  text ".plot_File_Name" at 14.656,-27.034 h1.52
  text "GENERATED    :" at 57.15,-27.034 h1.52
  text ".Print_Date" at 79.235,-27.034 h1.52
  text ".Print_Time" at 97.752,-27.034 h1.52
  text "TEXAS INSTRUMENTS" at 129.87,-27.034 h1.52
M12 Stackup:
  text ".Layer_Name" at 14.656,-21.806 h1.52
M13 Component Bodies Top:
  text ".Layer_Name" at 14.656,-21.806 h1.52
M14 Component Bodies Bottom:
  text ".Layer_Name" at 14.656,-21.806 h1.52
M15 Courtyards Top:
  text ".Layer_Name" at 14.656,-21.806 h1.52
M16 Courtyards Bottom:
  text ".Layer_Name" at 14.656,-21.806 h1.52
Drill Drawing:
  text ".Layer_Name" at 14.656,-21.806 h1.52
M17 Embedded Cavity:
  text ".Layer_Name" at 14.656,-21.806 h1.52
M18 Embedded Assembly:
  text ".Layer_Name" at 14.656,-21.806 h1.52
M19 Embedded Keepout:
  text ".Layer_Name" at 14.656,-21.806 h1.52

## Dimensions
0,3.5 to 40.5,3.2 on M2 Board Dimensions
0,-10.16 to 25.4,-10.16 on M2 Board Dimensions
34.5,3.5 to 40.55,70.5 on M2 Board Dimensions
